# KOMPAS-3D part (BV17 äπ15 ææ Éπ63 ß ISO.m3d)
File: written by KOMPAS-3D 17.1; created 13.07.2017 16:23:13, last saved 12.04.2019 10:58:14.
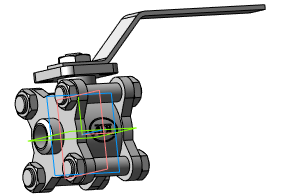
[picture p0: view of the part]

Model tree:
1. Операция без истории:3  (labels: Сталь 20  ГОСТ 1050-88)

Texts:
  DISO1
  DISO2
  BV17 Ду8 1/4" Ру63
  BV17 Ду8 СС Ру63
  BV17 Ду10 3/8" Ру63
  BV17 Ду10 СС Ру63
  BV17 Ду15 1/2" Ру63
  BV17 Ду15 СС Ру63
  BV17 Ду15 ФФ Ру40
  BV17 Ду20 3/4" Ру63
  BV17 Ду20 СС Ру40
  BV17 Ду20 ФФ Ру40
  BV17 Ду25 1" Ру63
  BV17 Ду25 СС Ру63
  BV17 Ду25 ФФ Ру40
  BV17 Ду32 1 1/4" Ру63
  BV17 Ду32 СС Ру63
  BV17 Ду32 ФФ Ру40
  BV17 Ду40 1 1/2" Ру63
  BV17 Ду40 СС Ру63
  BV17 Ду40 ФФ Ру40
  BV17 Ду50 2" Ру63
  BV17 Ду50 СС Ру63
  BV17 Ду50 ФФ Ру40
  BV17 Ду65 2 1/2" Ру40
  BV17 Ду65 СС Ру40
  BV17 Ду65 ФФ Ру40
  BV17 Ду80 3" Ру40
  BV17 Ду80 СС Ру40
  BV17 Ду80 ФФ Ру40
  BV17 Ду100 4" Ру40
  BV17 Ду100 СС Ру40
  BV17 Ду100 ФФ Ру40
